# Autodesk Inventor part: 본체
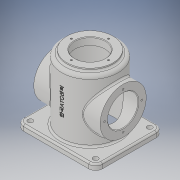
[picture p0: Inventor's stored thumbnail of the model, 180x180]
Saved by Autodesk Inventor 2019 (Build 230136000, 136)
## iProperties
Created: 2020-12
Part Number: 본체
Material: 일반
Document SubType Name: Modeling
Designer: jun-1-15
Density: 1 g/cm^3
Appearance: 기본값
Mass: 457.444 g
Surface Area: 1068.74 cm^2
Volume: 457.444 cm^3
Author: jun-1-15
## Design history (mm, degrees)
sketch "스케치1"
  geometry: C1 r 50 at (0, 0); 1 further point
  constraints: 1 centre point, 1 coincident
  dimensions: "d0" = 100 diameter of C1
extrude "돌출1" new body sketch "스케치1" distance "d1" = 120; taper "d2" = 0 deg
sketch "스케치2"
  geometry: L1 (70, -60)-(-70, -60); L2 (-70, -60)-(-70, 60); L3 (-70, 60)-(70, 60); L4 (70, 60)-(70, -60); L5 (70, -60)-(-70, 60); L6 (-70, -60)-(70, 60); C1 r 50 at (0, 0) reference; 1 further point
  constraints: 12 end point, 2 midpoint, 2 parallel, 1 horizontal, 1 perpendicular
  dimensions: "d3" = 140 distance of L2.end L3.end; "d4" = 120 distance of L1.end L2.end
extrude "돌출2" join sketch "스케치2" distance "d5" = 10; taper "d6" = 0 deg
sketch "스케치3"
  geometry: C1 r 41 at (0, 0); 1 further point
  constraints: 1 centre point, 1 coincident
  dimensions: "d7" = 82 diameter of C1
extrude "돌출3" join sketch "스케치3" distance "d8" = 5; taper "d9" = 0 deg
sketch "스케치4"
  geometry: 2 further points
  constraints: 1 coincident
hole "구멍1" sketch "스케치4" at (0, 0) diameter "d10" = 54; stored, may be unused: countersink angle "d14" = 90 deg, drill point angle "d16" = 0 deg; dims "d11" = 18, "d12" = 84, "d13" = 112, "d15" = 13
node "작업 평면1"
sketch "스케치5"
  geometry: L1 (0, -60)-(0, 60) reference; C1 r 41 at (60, 0); 2 further points
  constraints: 1 centre point, 1 horizontal alignment, 1 midpoint
  dimensions: "d18" = 82 diameter of C1; "d19" = 60 distance from line of L1 C1.centre
extrude "돌출4" join sketch "스케치5" stored distance "d20" = 15; taper "d21" = 0 deg
sketch "스케치7"
  geometry: C1 r 41 at (0, 0) reference; 2 further points
  constraints: 1 vertical alignment
  dimensions: "d29" = 33 distance of C1.centre point (0, 33)
hole "구멍3" sketch "스케치7" at (0, 33) diameter "d30" = 3.242; stored, may be unused: countersink angle "d34" = 90 deg, drill point angle "d36" = 118 deg; dims "d31" = 8, "d32" = 4, "d33" = 2, "d35" = 12
sketch "스케치8"
  geometry: C1 r 41 at (0, 0) reference; 2 further points
  constraints: 1 coincident
hole "구멍4" sketch "스케치8" at (0, 0) diameter "d40" = 54; stored, may be unused: countersink angle "d44" = 90 deg, drill point angle "d46" = 0 deg; dims "d41" = 8, "d42" = 4, "d43" = 2, "d45" = 12
fillet "모깎기1" dims "d47" = 12
sketch "스케치9"
  geometry: 2 further points
  constraints: 1 vertical alignment
  dimensions: "d48" = 33 distance of point (0, 0) point (0, 33)
hole "구멍5" sketch "스케치9" at (0, 33) diameter "d49" = 3.242; stored, may be unused: countersink angle "d53" = 90 deg, drill point angle "d55" = 118 deg; dims "d50" = 8, "d51" = 4, "d52" = 2, "d54" = 10
fillet "모깎기2" dims "d59" = 6
sketch "스케치10"
  geometry: A1 r 12 centre (-58, -48) between (-70, -48) and (-58, -60) reference; 2 further points
  constraints: 1 coincident
hole "구멍6" sketch "스케치10" at (-58, -48) diameter "d60" = 9; stored, may be unused: countersink angle "d64" = 90 deg, drill point angle "d66" = 118 deg; dims "d61" = 8, "d62" = 4, "d63" = 2, "d65" = 10
node "작업 평면3"
sketch "스케치11"
  geometry: L1 (58, 0)-(-58, 0) reference; 3 further points
  constraints: 1 midpoint, 1 vertical alignment, 1 other
  dimensions: "d67" = 70 distance from line of L1 point (0, 70)
feature "엠보싱1" sketch "스케치11" dims "d68" = 0.5, "d69" = 0
chamfer "모따기1" distance "d70" = 1; stored, may be unused: second distance "d71" = 2, angle "d72" = 45 deg
fillet "모깎기3" dims "d73" = 3
fillet "모깎기4" dims "d74" = 3
fillet "모깎기5" dims "d75" = 3
fillet "모깎기6" dims "d76" = 3
node "솔리드1"
pattern_circular "원형 패턴1" dims angle "d38" = 360 deg
mirror "미러1"
pattern_circular "원형 패턴2" dims angle "d57" = 360 deg
mirror "미러2"
mirror "미러3"
node "투영된 루프1"
node "투영된 루프2"
other parameters: "d17" = 59
